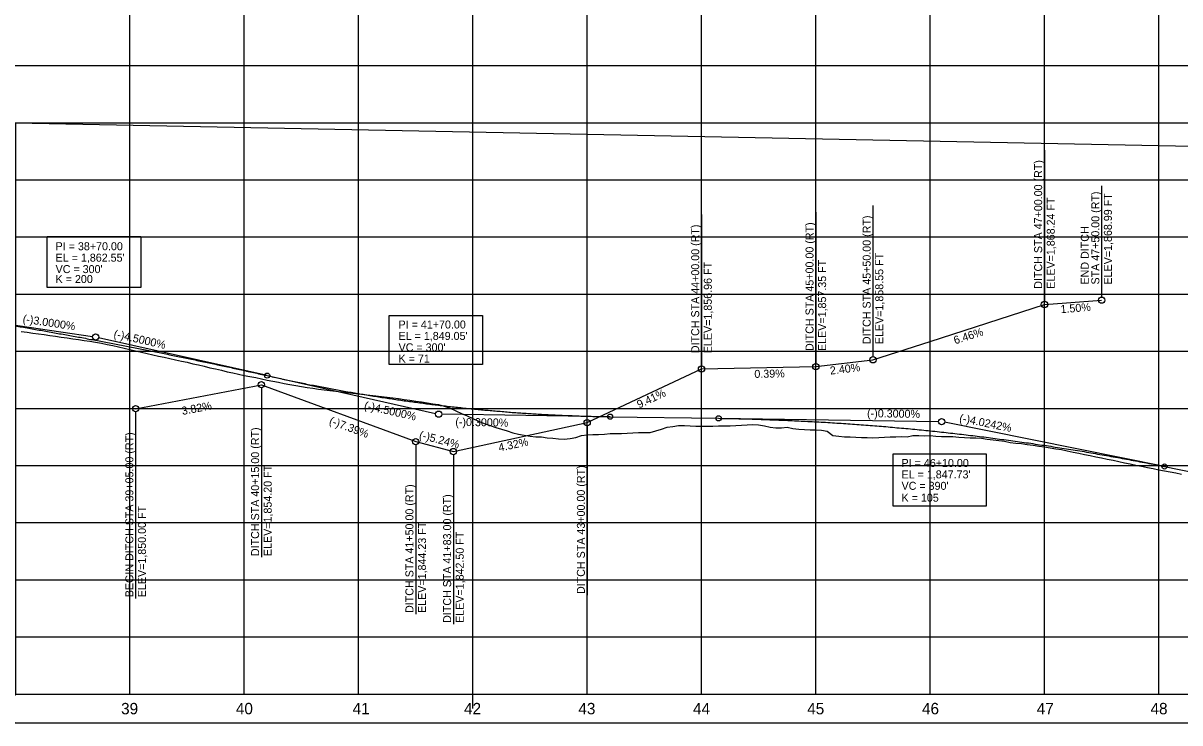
# Model space of a CAD drawing. Extents: x 553912 to 567693, y 512355 to 537539.
# Drawn here: x 560056 to 561068, y 513580 to 514193 of the extents above; entities that cross this region are included whole.
import ezdxf

# ---------------------------------------------------------------- set-up
doc = ezdxf.new("R2010")
doc.units = 0
for name, color, linetype in [('Exist Profile Cell', 7, 'Continuous'), ('Exist Vertical Profile Ground Line', 7, 'Continuous'), ('Exist Vertical Profile Horizontal Axis Label Major', 7, 'Continuous'), ('Prop Vertical Profile Curve Label', 7, 'Continuous'), ('Prop Vertical Profile Ditch Grade Right', 7, 'Continuous'), ('Prop Vertical Profile Ditch Grade Right Label', 7, 'Continuous'), ('Prop Vertical Profile Grade', 7, 'Continuous'), ('Prop Vertical Profile Grade Label', 7, 'Continuous'), ('Prop VPI Label', 7, 'Continuous'), ('Scratch_Level_1', 7, 'Continuous'), ('Scratch_Level_5', 7, 'Continuous'), ('Sheet Profile Grid Major CELL', 7, 'Continuous')]:
    doc.layers.add(name, color=color, linetype=linetype)

msp = doc.modelspace()

# ---------------------------------------------------------------- linework, layer by layer
at = {"layer": 'Exist Profile Cell'}
msp.add_line((557249.5, 513605.4), (563849.5, 513605.4), dxfattribs=at)
msp.add_line((557249.5, 513605.4), (563849.5, 513605.4), dxfattribs=at)
at = {"layer": 'Exist Vertical Profile Ground Line'}
for points in [[(560054.5, 513923.1), (560059.5, 513922.3), (560064.5, 513921.6), (560069.5, 513920.9), (560074.5, 513920.3), (560079.5, 513919.6), (560084.5, 513918.8), (560089.5, 513918.1), (560094.5, 513917.4), (560099.5, 513916.6), (560104.5, 513915.9), (560109.5, 513915.2), (560114.5, 513914.4), (560119.5, 513913.5), (560124.5, 513912.7), (560129.5, 513911.6), (560134.5, 513910.6), (560139.5, 513909.5), (560144.5, 513908.4), (560149.5, 513907.2), (560154.5, 513906.1), (560159.5, 513904.9), (560164.5, 513903.7), (560169.5, 513902.6), (560174.5, 513901.5), (560179.5, 513900.4), (560184.5, 513899.2), (560189.5, 513898.1), (560194.5, 513897.1), (560199.5, 513896), (560204.5, 513894.8), (560209.5, 513893.7), (560214.5, 513892.6), (560219.5, 513891.3), (560224.5, 513890.2), (560229.5, 513889.1), (560234.5, 513887.8), (560239.5, 513886.8), (560244.5, 513885.7), (560249.5, 513884.6)], [(560054.5, 513923.1), (560059.5, 513922.3), (560064.5, 513921.6), (560069.5, 513920.9), (560074.5, 513920.3), (560079.5, 513919.6), (560084.5, 513918.8), (560089.5, 513918.1), (560094.5, 513917.4), (560099.5, 513916.6), (560104.5, 513915.9), (560109.5, 513915.2), (560114.5, 513914.4), (560119.5, 513913.5), (560124.5, 513912.7), (560129.5, 513911.6), (560134.5, 513910.6), (560139.5, 513909.5), (560144.5, 513908.4), (560149.5, 513907.2), (560154.5, 513906.1), (560159.5, 513904.9), (560164.5, 513903.7), (560169.5, 513902.6), (560174.5, 513901.5), (560179.5, 513900.4), (560184.5, 513899.2), (560189.5, 513898.1), (560194.5, 513897.1), (560199.5, 513896), (560204.5, 513894.8), (560209.5, 513893.7), (560214.5, 513892.6), (560219.5, 513891.3), (560224.5, 513890.2), (560229.5, 513889.1), (560234.5, 513887.8), (560239.5, 513886.8), (560244.5, 513885.7), (560249.5, 513884.6)], [(560249.5, 513884.6), (560254.5, 513883.6), (560259.5, 513882.6), (560264.5, 513881.5), (560269.5, 513880.5), (560274.5, 513879.6), (560279.5, 513878.6), (560284.5, 513877.6), (560289.5, 513876.7), (560294.5, 513875.8), (560299.5, 513874.8), (560304.5, 513874.1), (560309.5, 513873.3), (560314.5, 513872.5), (560319.5, 513871.8), (560324.5, 513871.3), (560329.5, 513870.7), (560334.5, 513870.1), (560339.5, 513869.5), (560344.5, 513868.9), (560349.5, 513868.3), (560354.5, 513867.8), (560359.5, 513867.2), (560364.5, 513866.7), (560369.5, 513866), (560374.5, 513865.4), (560379.5, 513864.9), (560384.5, 513864.3), (560389.5, 513863.5), (560394.5, 513862.8), (560399.5, 513862.1), (560404.5, 513861.4), (560409.5, 513860.6), (560414.5, 513859.8), (560419.5, 513859), (560424.5, 513857.7), (560429.5, 513855.9), (560434.5, 513853.6), (560439.5, 513851.3), (560444.5, 513849.2), (560449.5, 513846.8), (560454.5, 513844.5), (560459.5, 513842.5), (560464.5, 513840.6), (560469.5, 513838.9), (560474.5, 513837.4), (560479.5, 513836), (560484.5, 513834.3), (560489.5, 513833), (560494.5, 513832.2), (560499.5, 513831.4), (560504.5, 513830.9), (560509.5, 513830.7), (560514.5, 513830), (560519.5, 513829.6), (560524.5, 513829.1), (560529.5, 513828.6), (560534.5, 513829.4), (560539.5, 513830.3), (560544.5, 513831.9), (560549.5, 513832.6), (560554.5, 513832.8), (560559.5, 513832.9), (560564.5, 513833.2), (560569.5, 513833.6), (560574.5, 513833.8), (560579.5, 513833.8), (560584.5, 513834.1), (560589.5, 513834.4), (560594.5, 513834.6), (560599.5, 513834.6), (560604.5, 513834.5), (560609.5, 513835.9), (560614.5, 513837.4), (560619.5, 513839.1), (560624.5, 513839.7), (560629.5, 513840.7), (560634.5, 513840.7), (560639.5, 513840.4), (560644.5, 513840.2), (560649.5, 513840.1), (560654.5, 513840.1), (560659.5, 513840.2), (560664.5, 513840.3), (560669.5, 513840.4), (560674.5, 513840.4), (560679.5, 513840.6), (560684.5, 513841), (560689.5, 513841.4), (560694.5, 513841.5), (560699.5, 513841.2), (560704.5, 513840.4), (560709.5, 513839.3), (560714.5, 513838.6), (560719.5, 513838.7), (560724.5, 513839.1), (560729.5, 513838.2), (560734.5, 513837.5), (560739.5, 513837.1), (560744.5, 513837), (560749.5, 513836.9)], [(560249.5, 513884.6), (560254.5, 513883.6), (560259.5, 513882.6), (560264.5, 513881.5), (560269.5, 513880.5), (560274.5, 513879.6), (560279.5, 513878.6), (560284.5, 513877.6), (560289.5, 513876.7), (560294.5, 513875.8), (560299.5, 513874.8), (560304.5, 513874.1), (560309.5, 513873.3), (560314.5, 513872.5), (560319.5, 513871.8), (560324.5, 513871.3), (560329.5, 513870.7), (560334.5, 513870.1), (560339.5, 513869.5), (560344.5, 513868.9), (560349.5, 513868.3), (560354.5, 513867.8), (560359.5, 513867.2), (560364.5, 513866.7), (560369.5, 513866), (560374.5, 513865.4), (560379.5, 513864.9), (560384.5, 513864.3), (560389.5, 513863.5), (560394.5, 513862.8), (560399.5, 513862.1), (560404.5, 513861.4), (560409.5, 513860.6), (560414.5, 513859.8), (560419.5, 513859), (560424.5, 513857.7), (560429.5, 513855.9), (560434.5, 513853.6), (560439.5, 513851.3), (560444.5, 513849.2), (560449.5, 513846.8), (560454.5, 513844.5), (560459.5, 513842.5), (560464.5, 513840.6), (560469.5, 513838.9), (560474.5, 513837.4), (560479.5, 513836), (560484.5, 513834.3), (560489.5, 513833), (560494.5, 513832.2), (560499.5, 513831.4), (560504.5, 513830.9), (560509.5, 513830.7), (560514.5, 513830), (560519.5, 513829.6), (560524.5, 513829.1), (560529.5, 513828.6), (560534.5, 513829.4), (560539.5, 513830.3), (560544.5, 513831.9), (560549.5, 513832.6), (560554.5, 513832.8), (560559.5, 513832.9), (560564.5, 513833.2), (560569.5, 513833.6), (560574.5, 513833.8), (560579.5, 513833.8), (560584.5, 513834.1), (560589.5, 513834.4), (560594.5, 513834.6), (560599.5, 513834.6), (560604.5, 513834.5), (560609.5, 513835.9), (560614.5, 513837.4), (560619.5, 513839.1), (560624.5, 513839.7), (560629.5, 513840.7), (560634.5, 513840.7), (560639.5, 513840.4), (560644.5, 513840.2), (560649.5, 513840.1), (560654.5, 513840.1), (560659.5, 513840.2), (560664.5, 513840.3), (560669.5, 513840.4), (560674.5, 513840.4), (560679.5, 513840.6), (560684.5, 513841), (560689.5, 513841.4), (560694.5, 513841.5), (560699.5, 513841.2), (560704.5, 513840.4), (560709.5, 513839.3), (560714.5, 513838.6), (560719.5, 513838.7), (560724.5, 513839.1), (560729.5, 513838.2), (560734.5, 513837.5), (560739.5, 513837.1), (560744.5, 513837), (560749.5, 513836.9)], [(560749.5, 513836.9), (560754.5, 513836.5), (560759.5, 513835.6), (560764.5, 513831.9), (560769.5, 513831.4), (560774.5, 513830.9), (560779.5, 513830.8), (560784.5, 513830.6), (560789.5, 513830.2), (560794.5, 513830.1), (560799.5, 513830), (560804.5, 513830.1), (560809.5, 513830.4), (560814.5, 513830.7), (560819.5, 513830.7), (560824.5, 513831), (560829.5, 513830.8), (560834.5, 513831.8), (560839.5, 513832), (560844.5, 513831.6), (560849.5, 513831.9), (560854.5, 513831.5), (560859.5, 513831.2), (560864.5, 513831.2), (560869.5, 513831.2), (560874.5, 513830.5), (560879.5, 513830.2), (560884.5, 513829.9), (560889.5, 513830), (560894.5, 513829.5), (560899.5, 513828.8), (560904.5, 513828.2), (560909.5, 513827.6), (560914.5, 513826.9), (560919.5, 513825.9), (560924.5, 513825.3), (560929.5, 513824.9), (560934.5, 513824.2), (560939.5, 513823.5), (560944.5, 513822.7), (560949.5, 513821.9), (560954.5, 513821.1), (560959.5, 513820.3), (560964.5, 513819.6), (560969.5, 513818.6), (560974.5, 513817.5), (560979.5, 513816.5), (560984.5, 513815.4), (560989.5, 513814.3), (560994.5, 513813.4), (560999.5, 513812.3), (561004.5, 513811.3), (561009.5, 513810.3), (561014.5, 513809.2), (561019.5, 513808.1), (561024.5, 513807.1), (561029.5, 513806.1), (561034.5, 513805), (561039.5, 513804), (561044.5, 513803), (561049.5, 513802), (561054.5, 513801.1), (561059.5, 513800.1), (561064.5, 513799.2), (561069.5, 513798.2)], [(560749.5, 513836.9), (560754.5, 513836.5), (560759.5, 513835.6), (560764.5, 513831.9), (560769.5, 513831.4), (560774.5, 513830.9), (560779.5, 513830.8), (560784.5, 513830.6), (560789.5, 513830.2), (560794.5, 513830.1), (560799.5, 513830), (560804.5, 513830.1), (560809.5, 513830.4), (560814.5, 513830.7), (560819.5, 513830.7), (560824.5, 513831), (560829.5, 513830.8), (560834.5, 513831.8), (560839.5, 513832), (560844.5, 513831.6), (560849.5, 513831.9), (560854.5, 513831.5), (560859.5, 513831.2), (560864.5, 513831.2), (560869.5, 513831.2), (560874.5, 513830.5), (560879.5, 513830.2), (560884.5, 513829.9), (560889.5, 513830), (560894.5, 513829.5), (560899.5, 513828.8), (560904.5, 513828.2), (560909.5, 513827.6), (560914.5, 513826.9), (560919.5, 513825.9), (560924.5, 513825.3), (560929.5, 513824.9), (560934.5, 513824.2), (560939.5, 513823.5), (560944.5, 513822.7), (560949.5, 513821.9), (560954.5, 513821.1), (560959.5, 513820.3), (560964.5, 513819.6), (560969.5, 513818.6), (560974.5, 513817.5), (560979.5, 513816.5), (560984.5, 513815.4), (560989.5, 513814.3), (560994.5, 513813.4), (560999.5, 513812.3), (561004.5, 513811.3), (561009.5, 513810.3), (561014.5, 513809.2), (561019.5, 513808.1), (561024.5, 513807.1), (561029.5, 513806.1), (561034.5, 513805), (561039.5, 513804), (561044.5, 513803), (561049.5, 513802), (561054.5, 513801.1), (561059.5, 513800.1), (561064.5, 513799.2), (561069.5, 513798.2)]]:
    msp.add_lwpolyline(points, dxfattribs=at)
at = {"layer": 'Prop Vertical Profile Curve Label'}
for centre in [(560269.5, 513884.4), (560269.5, 513884.4), (560569.5, 513848.4), (560664.5, 513847), (561054.5, 513804.8)]:
    msp.add_circle(centre, 2.25, dxfattribs=at)
at = {"layer": 'Prop Vertical Profile Ditch Grade Right'}
for p, q in [((560949.5, 513946.6), (560999.5, 513950.4)), ((560849.5, 513914.3), (560949.5, 513946.6))]:
    msp.add_line(p, q, dxfattribs=at)
for points in [[(560549.5, 513843.2), (560649.5, 513890.2), (560749.5, 513892.2), (560799.5, 513898.2), (560849.5, 513914.3)], [(560154.5, 513855.4), (560264.5, 513876.4), (560399.5, 513826.6)], [(560399.5, 513826.6), (560432.5, 513817.9), (560549.5, 513843.2)]]:
    msp.add_lwpolyline(points, dxfattribs=at)
at = {"layer": 'Prop Vertical Profile Ditch Grade Right Label'}
for p, q in [((560949.5, 514081.8), (560949.5, 513949.4)), ((560999.5, 514050.5), (560999.5, 513953.1)), ((560799.5, 514033.3), (560799.5, 513900.9)), ((560649.5, 514025.4), (560649.5, 513893)), ((560749.5, 514027.3), (560749.5, 513894.9)), ((560264.5, 513873.7), (560264.5, 513725.4)), ((560154.5, 513852.7), (560154.5, 513689.4)), ((560549.5, 513840.4), (560549.5, 513692.2)), ((560399.5, 513823.8), (560399.5, 513675.6)), ((560432.5, 513815.2), (560432.5, 513666.9))]:
    msp.add_line(p, q, dxfattribs=at)
for centre in [(560949.5, 513946.6), (560999.5, 513950.4), (560799.5, 513898.2), (560649.5, 513890.2), (560749.5, 513892.2), (560264.5, 513876.4), (560154.5, 513855.4), (560154.5, 513855.4), (560549.5, 513843.2), (560549.5, 513843.2), (560549.5, 513843.2), (560399.5, 513826.6), (560432.5, 513817.9)]:
    msp.add_circle(centre, 2.75, dxfattribs=at)
at = {"layer": 'Prop Vertical Profile Grade'}
for p, q in [((560569.5, 513848.4), (560664.5, 513847)), ((561054.5, 513804.8), (561081.5, 513799.4))]:
    msp.add_line(p, q, dxfattribs=at)
for points in [[(559969.5, 513940.6), (559975.5, 513939.7), (559981.5, 513938.8), (559987.5, 513937.9), (559993.5, 513937), (559999.5, 513936), (560005.5, 513935.1), (560011.5, 513934.1), (560017.5, 513933.2), (560023.5, 513932.2), (560029.5, 513931.2), (560035.5, 513930.2), (560041.5, 513929.2), (560047.5, 513928.2), (560053.5, 513927.2), (560059.5, 513926.1), (560065.5, 513925.1), (560071.5, 513924), (560077.5, 513923), (560083.5, 513921.9), (560089.5, 513920.8), (560095.5, 513919.8), (560101.5, 513918.7), (560107.5, 513917.6), (560113.5, 513916.4), (560119.5, 513915.3), (560125.5, 513914.2), (560131.5, 513913.1), (560137.5, 513911.9), (560143.5, 513910.8), (560149.5, 513909.6), (560155.5, 513908.4), (560161.5, 513907.2), (560167.5, 513906), (560173.5, 513904.8), (560179.5, 513903.6), (560185.5, 513902.4), (560191.5, 513901.2), (560197.5, 513899.9), (560203.5, 513898.7), (560209.5, 513897.4), (560215.5, 513896.2), (560221.5, 513894.9), (560227.5, 513893.6), (560233.5, 513892.3), (560239.5, 513891), (560245.5, 513889.7), (560251.5, 513888.4), (560257.5, 513887.1), (560263.5, 513885.7), (560269.5, 513884.4)], [(560269.5, 513884.4), (560275.5, 513883.1), (560281.5, 513881.7), (560287.5, 513880.5), (560293.5, 513879.2), (560299.5, 513878), (560305.5, 513876.7), (560311.5, 513875.6), (560317.5, 513874.4), (560323.5, 513873.3), (560329.5, 513872.1), (560335.5, 513871.1), (560341.5, 513870), (560347.5, 513869), (560353.5, 513868), (560359.5, 513867), (560365.5, 513866), (560371.5, 513865.1), (560377.5, 513864.2), (560383.5, 513863.3), (560389.5, 513862.4), (560395.5, 513861.6), (560401.5, 513860.8), (560407.5, 513860), (560413.5, 513859.2), (560419.5, 513858.5), (560425.5, 513857.8), (560431.5, 513857.1), (560437.5, 513856.5), (560443.5, 513855.8), (560449.5, 513855.2), (560455.5, 513854.6), (560461.5, 513854.1), (560467.5, 513853.6), (560473.5, 513853.1), (560479.5, 513852.6), (560485.5, 513852.1), (560491.5, 513851.7), (560497.5, 513851.3), (560503.5, 513850.9), (560509.5, 513850.5), (560515.5, 513850.2), (560521.5, 513849.9), (560527.5, 513849.6), (560533.5, 513849.4), (560539.5, 513849.2), (560545.5, 513848.9), (560551.5, 513848.8), (560557.5, 513848.6), (560563.5, 513848.5), (560569.5, 513848.4)], [(560664.5, 513847), (560672.3, 513846.8), (560680.1, 513846.7), (560687.9, 513846.5), (560695.7, 513846.3), (560703.5, 513846), (560711.3, 513845.7), (560719.1, 513845.4), (560726.9, 513845.1), (560734.7, 513844.7), (560742.5, 513844.3), (560750.3, 513843.9), (560758.1, 513843.5), (560765.9, 513843), (560773.7, 513842.5), (560781.5, 513841.9), (560789.3, 513841.4), (560797.1, 513840.8), (560804.9, 513840.2), (560812.7, 513839.5), (560820.5, 513838.8), (560828.3, 513838.1), (560836.1, 513837.4), (560843.9, 513836.6), (560851.7, 513835.8), (560859.5, 513835), (560867.3, 513834.1), (560875.1, 513833.2), (560882.9, 513832.3), (560890.7, 513831.4), (560898.5, 513830.4), (560906.3, 513829.4), (560914.1, 513828.3), (560921.9, 513827.3), (560929.7, 513826.2), (560937.5, 513825.1), (560945.3, 513823.9), (560953.1, 513822.8), (560960.9, 513821.5), (560968.7, 513820.3), (560976.5, 513819), (560984.3, 513817.8), (560992.1, 513816.4), (560999.9, 513815.1), (561007.7, 513813.7), (561015.5, 513812.3), (561023.3, 513810.8), (561031.1, 513809.4), (561038.9, 513807.9), (561046.7, 513806.4), (561054.5, 513804.8)]]:
    msp.add_spline(points, degree=3, dxfattribs=at)
at = {"layer": 'Prop VPI Label'}
for p, q in [((559969.5, 513940.6), (560116.7, 513918.5)), ((560269.5, 513884.4), (560122.1, 513917.5)), ((560269.5, 513884.4), (560416.8, 513851.2)), ((560569.5, 513848.4), (560422.2, 513850.6)), ((560664.5, 513847), (560856.7, 513844.1)), ((561054.5, 513804.8), (560862.1, 513843.5))]:
    msp.add_line(p, q, dxfattribs=at)
for points in [[(560077.1, 514006), (560159, 514006), (560159, 513961.5), (560077.1, 513961.5)], [(560376.2, 513936.9), (560458, 513936.9), (560458, 513894.1), (560376.2, 513894.1)], [(560817.1, 513816), (560898.5, 513816), (560898.5, 513770.1), (560817.1, 513770.1)]]:
    msp.add_lwpolyline(points, close=True, dxfattribs=at)
for centre in [(560119.5, 513918.1), (560419.5, 513850.6), (560859.5, 513844)]:
    msp.add_circle(centre, 2.75, dxfattribs=at)
at = {"layer": 'Scratch_Level_1'}
msp.add_line((560449.5, 513592.9), (560449.5, 513937.1), dxfattribs=at)
at = {"layer": 'Scratch_Level_5'}
msp.add_lwpolyline([(561299.4, 514080.4), (560049.5, 514105.4), (560049.5, 513605.4), (560036.6, 513588.8), (560049.5, 513580.4), (561449.5, 513580.4), (561462.7, 513590.1), (561449.5, 513605.4), (561449.5, 513944.4), (561299.4, 513944.4)], close=True, dxfattribs=at)
at = {"layer": 'Sheet Profile Grid Major CELL'}
for p, q in [((560149.5, 513605.4), (560149.5, 514805.4)), ((560249.5, 513605.4), (560249.5, 514805.4)), ((560349.5, 513605.4), (560349.5, 514805.4)), ((560449.5, 513605.4), (560449.5, 514805.4)), ((560549.5, 513605.4), (560549.5, 514805.4)), ((560649.5, 513605.4), (560649.5, 514805.4)), ((560749.5, 513605.4), (560749.5, 514805.4)), ((560849.5, 513605.4), (560849.5, 514805.4)), ((560949.5, 513605.4), (560949.5, 514805.4)), ((561049.5, 513605.4), (561049.5, 514805.4)), ((563849.5, 514155.4), (557249.5, 514155.4)), ((563849.5, 514105.4), (557249.5, 514105.4)), ((563849.5, 514055.4), (557249.5, 514055.4)), ((563849.5, 514005.4), (557249.5, 514005.4)), ((563849.5, 513955.4), (557249.5, 513955.4)), ((563849.5, 513905.4), (557249.5, 513905.4)), ((563849.5, 513855.4), (557249.5, 513855.4)), ((563849.5, 513805.4), (557249.5, 513805.4)), ((563849.5, 513755.4), (557249.5, 513755.4)), ((563849.5, 513705.4), (557249.5, 513705.4)), ((563849.5, 513655.4), (557249.5, 513655.4))]:
    msp.add_line(p, q, dxfattribs=at)

# ---------------------------------------------------------------- texts
at = {"layer": 'Exist Vertical Profile Horizontal Axis Label Major'}
for s, p in [('39', (560141.8, 513587.9)), ('39', (560141.8, 513587.9)), ('40', (560242.2, 513587.9)), ('40', (560242.2, 513587.9)), ('41', (560344.3, 513587.9)), ('41', (560344.3, 513587.9)), ('42', (560441.8, 513587.9)), ('42', (560441.8, 513587.9)), ('43', (560541.8, 513587.9)), ('43', (560541.8, 513587.9)), ('44', (560642.1, 513587.9)), ('44', (560642.1, 513587.9)), ('45', (560742, 513587.9)), ('45', (560742, 513587.9)), ('46', (560842.4, 513587.9)), ('46', (560842.4, 513587.9)), ('47', (560942.8, 513587.9)), ('47', (560942.8, 513587.9)), ('48', (561042.3, 513587.9)), ('48', (561042.3, 513587.9))]:
    msp.add_text(s, height=10, dxfattribs=at).set_placement(p)
at = {"layer": 'Prop Vertical Profile Curve Label'}
for s, p in [("VC = 300'", (560084.5, 513974.1)), ('K = 200', (560084.5, 513965.4)), ("VC = 300'", (560384.5, 513905.6)), ('K = 71', (560384.5, 513895.8)), ("VC = 390'", (560824.5, 513784.4)), ('K = 105', (560824.5, 513774))]:
    msp.add_text(s, height=7, dxfattribs=at).set_placement(p)
at = {"layer": 'Prop Vertical Profile Ditch Grade Right'}
for s, p in [('DITCH STA 47+00.00 (RT)', (560947.5, 513960.4)), ('STA 47+50.00 (RT)', (560997.5, 513964.1)), ('DITCH STA 45+00.00 (RT)', (560747.5, 513905.9)), ('DITCH STA 45+50.00 (RT)', (560797.5, 513911.9)), ('DITCH STA 44+00.00 (RT)', (560647.5, 513904)), ('END DITCH', (560988.3, 513964.1)), ('DITCH STA 40+15.00 (RT)', (560262.5, 513726.4)), ('BEGIN DITCH STA 39+05.00 (RT)', (560152.5, 513690.4)), ('DITCH STA 43+00.00 (RT)', (560547.5, 513693.2)), ('DITCH STA 41+50.00 (RT)', (560397.5, 513676.6)), ('DITCH STA 41+83.00 (RT)', (560430.5, 513667.9))]:
    msp.add_text(s, height=7, rotation=90, dxfattribs=at).set_placement(p)
at = {"layer": 'Prop Vertical Profile Ditch Grade Right Label'}
for s, rotation, p in [('ELEV=1,868.24 FT', 90, (560958.5, 513960.4)), ('ELEV=1,868.99 FT', 90, (561008.5, 513964.1)), ('ELEV=1,858.55 FT', 90, (560808.5, 513911.9)), ('ELEV=1,856.96 FT', 90, (560658.5, 513904)), ('ELEV=1,857.35 FT', 90, (560758.5, 513905.9)), ('1.50%', 4.2892, (560963.8, 513939)), ('6.46%', 17.9005, (560871.4, 513911.7)), ('0.39%', 1.1171, (560695.8, 513882.3)), ('2.40%', 6.8428, (560762.3, 513885.2)), ('9.41%', 25.197, (560595, 513855.5)), ('3.82%', 10.8082, (560195.5, 513849.9)), ('(-)7.39%', 339.7329, (560323.2, 513842.1)), ('(-)5.24%', 345.312, (560402, 513829.5)), ('4.32%', 12.1783, (560472.6, 513817.8)), ('ELEV=1,854.20 FT', 90, (560273.5, 513726.4)), ('ELEV=1,850.00 FT', 90, (560163.5, 513690.4)), ('ELEV=1,844.23 FT', 90, (560408.5, 513676.6)), ('ELEV=1,842.50 FT', 90, (560441.5, 513667.9))]:
    msp.add_text(s, height=7, rotation=rotation, dxfattribs=at).set_placement(p)
at = {"layer": 'Prop Vertical Profile Grade Label'}
for s, rotation, p in [('(-)3.0000%', 351.4692, (560055.4, 513930.8)), ('(-)4.5000%', 347.3196, (560134.8, 513917.8)), ('(-)4.5000%', 347.3196, (560353.9, 513855.1)), ('(-)0.3000%', 359.1406, (560434.1, 513840.4)), ('(-)0.3000%', 359.1406, (560794.3, 513848)), ('(-)4.0242%', 348.6235, (560874.6, 513844.1))]:
    msp.add_text(s, height=7, rotation=rotation, dxfattribs=at).set_placement(p)
at = {"layer": 'Prop VPI Label'}
for s, p in [('PI = 38+70.00', (560084.5, 513994.1)), ("EL = 1,862.55'", (560084.5, 513984.1)), ('PI = 41+70.00', (560384.5, 513925.6)), ("EL = 1,849.05'", (560384.5, 513915.6)), ('PI = 46+10.00', (560824.5, 513804.4)), ("EL = 1,847.73'", (560824.5, 513794.4))]:
    msp.add_text(s, height=7, dxfattribs=at).set_placement(p)

doc.saveas('drawing.dxf')
